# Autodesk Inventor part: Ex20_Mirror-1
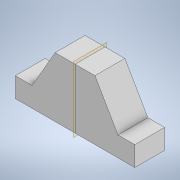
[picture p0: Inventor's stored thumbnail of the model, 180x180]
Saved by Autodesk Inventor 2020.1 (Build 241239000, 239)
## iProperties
Created: 2019-11
Part Number: Ex20_Mirror-1
Material: Generic
Document SubType Name: Modeling
Designer: Synergysoft Dell02
Density: 1 g/cm^3
Appearance: Default
Author: Synergysoft Dell02
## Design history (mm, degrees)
sketch "Sketch1"
  geometry: L1 (0, 30)-(-10, 30); L2 (-10, 30)-(-21.547, 10); L3 (-21.547, 10)-(-30, 10); L4 (-30, 10)-(-30, 0); L5 (-30, 0)-(0, 0); L6 (0, 0)-(0, 30)
  constraints: 12 end point, 3 perpendicular, 1 horizontal, 1 parallel
  dimensions: "d0" = 10 distance between parallel lines of L5 L3; "d1" = 30 deg angle of L6 L2; "d2" = 30 distance of L5.end L1.start; "d3" = 30 distance between parallel lines of L6 L4; "d4" = 10 distance of L1.start L1.end
extrude "Extrusion1" new body sketch "Sketch1" distance "d5" = 15; taper "d6" = 0 deg
mirror "Mirror1"
body "Solid1"
feature "Pattern of Solid1:1"
body "Solid2"
